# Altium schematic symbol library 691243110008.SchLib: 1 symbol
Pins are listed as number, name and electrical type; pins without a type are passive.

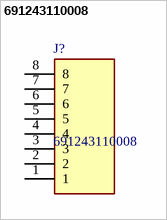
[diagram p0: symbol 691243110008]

## 691243110008
designator J?
WR-TBL Series 2431 - 3.50 mm Horizontal cable entry with rising clamp 8 Way PCB Terminal Block; Manufacturer_Name: Wurth Elektronik; Geometry.Height: 9.2mm
footprint 691243110008
pins: 1, 2, 3, 4, 5, 6, 7, 8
